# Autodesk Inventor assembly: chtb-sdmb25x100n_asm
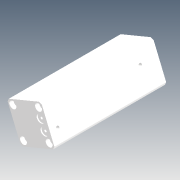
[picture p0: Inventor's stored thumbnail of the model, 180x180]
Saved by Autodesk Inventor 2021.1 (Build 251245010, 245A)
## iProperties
Company: Microsoft
Created: 2018-05
Part Number: chtb-sdmb25x100n_asm
Description: STEP AP214
Document SubType Name: Assembly
Designer: user
Title: chtb-sdmb25x100n_asm.STEP
Author: Windows
Revision Number: ÈÎºÎ
Sending System: SolidWorks 2015
Preprocessor: SwSTEP 2.0
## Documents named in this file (4)
- D:\Vault_2016\Projekty\Clamptek\Hydraulic\CHTB\CHTB-25\Inventor\chtb-sdmb25x100n\chtb-sdmb25x100n_asm.iam
- D:\Vault_2016\Projekty\Clamptek\Hydraulic\CHTB\CHTB-25\Inventor\chtb-sdmb25x100n\CHTB-25QG.ipt
- D:\Vault_2016\Projekty\Clamptek\Hydraulic\CHTB\CHTB-25\Inventor\chtb-sdmb25x100n\CHTB-SDMB25X100NBT.ipt
- D:\Vault_2016\Projekty\Clamptek\Hydraulic\CHTB\CHTB-25\Inventor\chtb-sdmb25x100n\CHTB-SDMB25X100NHSG.ipt
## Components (3 placed, 3 different names)
1. CHTB-25QG_1
2. CHTB-SDMB25X100NBT_2
3. CHTB-SDMB25X100NHSG_3
